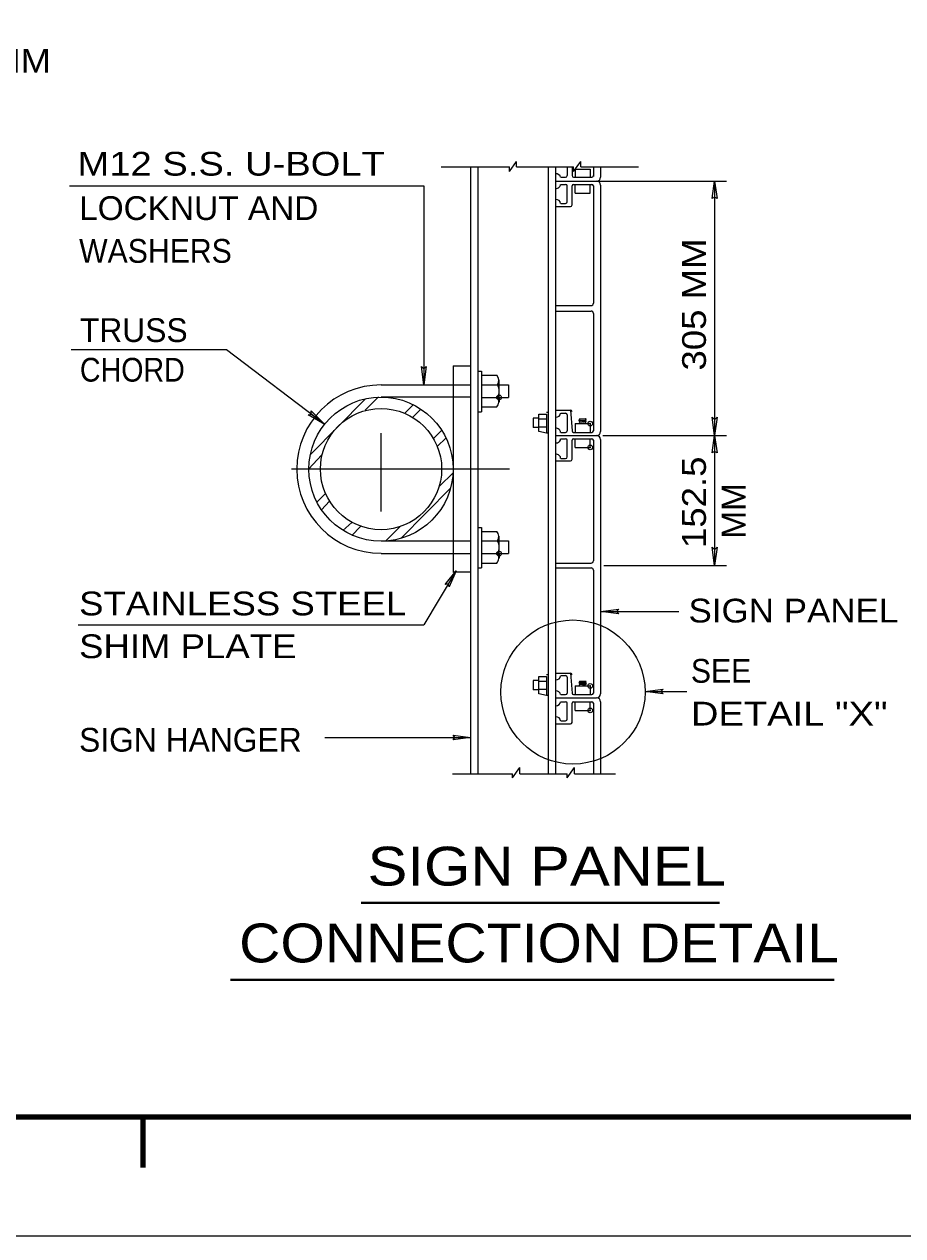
# Model space of a CAD drawing. Extents: x 312601.858 to 312602.699, y 144420.109 to 144420.704.
# Drawn here: x 312602.2633 to 312602.3741, y 144420.1095 to 144420.2624 of the extents above; entities that cross this region are included whole.
import ezdxf
from ezdxf.enums import TextEntityAlignment as Align

# ---------------------------------------------------------------- set-up
doc = ezdxf.new("R2010")
doc.units = 0
doc.header["$LTSCALE"] = 0.0012
doc.header["$PDMODE"] = 32
doc.header["$PDSIZE"] = 0.0006
doc.linetypes.add('DOT_DASHED', pattern=[7.7, 5, -1.2, 0.3, -1.2])
doc.linetypes.add('SHORT_DASHED', pattern=[2.7, 1.5, -1.2])
for name, color, linetype, lineweight in [('1', 7, 'Continuous', 13), ('2', 7, 'Continuous', 13), ('39', 7, 'Continuous', 13)]:
    doc.layers.add(name, color=color, linetype=linetype, lineweight=lineweight)

msp = doc.modelspace()

# ---------------------------------------------------------------- hatches: boundary and pattern name
at = {"layer": '39'}
msp.add_hatch(color=256, dxfattribs=at).paths.add_polyline_path([(312602.2995, 144420.2132), (312602.2995, 144420.2136), (312602.3012, 144420.2119), (312602.2991, 144420.2131)])

# ---------------------------------------------------------------- linework, layer by layer
at = {"layer": '1'}
for p, q in [((312602.3159, 144420.2444), (312602.3245, 144420.2444)), ((312602.3245, 144420.2438), (312602.3254, 144420.2451)), ((312602.3245, 144420.2438), (312602.3245, 144420.2444)), ((312602.3254, 144420.2444), (312602.3254, 144420.2451)), ((312602.3254, 144420.2444), (312602.3326, 144420.2444)), ((312602.3326, 144420.2438), (312602.3335, 144420.2451)), ((312602.3326, 144420.2438), (312602.3326, 144420.2444)), ((312602.3335, 144420.2444), (312602.3335, 144420.2451)), ((312602.3335, 144420.2444), (312602.3408, 144420.2444)), ((312602.3351, 144420.2444), (312602.3351, 144420.2432)), ((312602.3328, 144420.2441), (312602.3328, 144420.2431)), ((312602.3328, 144420.2441), (312602.3347, 144420.2441)), ((312602.3347, 144420.2441), (312602.3347, 144420.2431)), ((312602.269, 144420.242), (312602.3137, 144420.242)), ((312602.3137, 144420.242), (312602.3137, 144420.2169)), ((312602.331, 144420.2422), (312602.3316, 144420.2422)), ((312602.3318, 144420.24), (312602.3318, 144420.242)), ((312602.3328, 144420.2411), (312602.3328, 144420.2422)), ((312602.3328, 144420.2411), (312602.3347, 144420.2411)), ((312602.3347, 144420.2411), (312602.3347, 144420.2422)), ((312602.331, 144420.2398), (312602.3316, 144420.2398)), ((312602.2994, 144420.2081), (312602.3063, 144420.2151)), ((312602.3063, 144420.2137), (312602.308, 144420.2154)), ((312602.3113, 144420.2133), (312602.3124, 144420.2144)), ((312602.3123, 144420.2128), (312602.3133, 144420.2138)), ((312602.3275, 144420.2127), (312602.3275, 144420.2115)), ((312602.3282, 144420.2127), (312602.3275, 144420.2127)), ((312602.3282, 144420.2126), (312602.3292, 144420.2126)), ((312602.3294, 144420.2134), (312602.3292, 144420.2134)), ((312602.331, 144420.2133), (312602.3316, 144420.2133)), ((312602.3318, 144420.2131), (312602.3318, 144420.2111)), ((312602.3333, 144420.2126), (312602.3334, 144420.2126)), ((312602.3333, 144420.2124), (312602.3341, 144420.2124)), ((312602.3334, 144420.2126), (312602.3341, 144420.2126)), ((312602.3334, 144420.2122), (312602.3342, 144420.2123)), ((312602.3149, 144420.2101), (312602.316, 144420.2112)), ((312602.3282, 144420.2115), (312602.3275, 144420.2115)), ((312602.3282, 144420.2116), (312602.3292, 144420.2116)), ((312602.3294, 144420.2108), (312602.3292, 144420.2108)), ((312602.331, 144420.2109), (312602.3316, 144420.2109)), ((312602.3327, 144420.2109), (312602.3349, 144420.2109)), ((312602.3328, 144420.212), (312602.3328, 144420.2109)), ((312602.3328, 144420.212), (312602.3347, 144420.212)), ((312602.3347, 144420.212), (312602.3347, 144420.2109)), ((312602.3363, 144420.2105), (312602.3519, 144420.2105)), ((312602.3154, 144420.2091), (312602.3165, 144420.2102)), ((312602.331, 144420.2101), (312602.3316, 144420.2101)), ((312602.3318, 144420.2078), (312602.3318, 144420.2099)), ((312602.3327, 144420.2101), (312602.3349, 144420.2101)), ((312602.3328, 144420.209), (312602.3328, 144420.2101)), ((312602.3328, 144420.209), (312602.3347, 144420.209)), ((312602.3347, 144420.209), (312602.3347, 144420.2101)), ((312602.2992, 144420.2063), (312602.3008, 144420.208)), ((312602.331, 144420.2076), (312602.3316, 144420.2076)), ((312602.3157, 144420.2041), (312602.3174, 144420.2058)), ((312602.3002, 144420.2021), (312602.3013, 144420.2032)), ((312602.3108, 144420.1975), (312602.3171, 144420.2039)), ((312602.3008, 144420.2011), (312602.3018, 144420.2022)), ((312602.3035, 144420.1985), (312602.3046, 144420.1995)), ((312602.3046, 144420.1979), (312602.3057, 144420.199)), ((312602.3089, 144420.1972), (312602.3107, 144420.199)), ((312602.3364, 144420.1941), (312602.3519, 144420.1941)), ((312602.3177, 144420.1933), (312602.3137, 144420.1866)), ((312602.336, 144420.1883), (312602.3459, 144420.1883)), ((312602.2701, 144420.1866), (312602.3137, 144420.1866)), ((312602.3294, 144420.1803), (312602.3292, 144420.1803)), ((312602.331, 144420.1802), (312602.3316, 144420.1802)), ((312602.3318, 144420.18), (312602.3318, 144420.178)), ((312602.3275, 144420.1796), (312602.3275, 144420.1784)), ((312602.3282, 144420.1796), (312602.3275, 144420.1796)), ((312602.3282, 144420.1784), (312602.3275, 144420.1784)), ((312602.3282, 144420.1795), (312602.3292, 144420.1795)), ((312602.3282, 144420.1785), (312602.3292, 144420.1785)), ((312602.3328, 144420.1789), (312602.3328, 144420.1778)), ((312602.3328, 144420.1789), (312602.3347, 144420.1789)), ((312602.3333, 144420.1794), (312602.3334, 144420.1795)), ((312602.3333, 144420.1792), (312602.3341, 144420.1792)), ((312602.3334, 144420.1795), (312602.3342, 144420.1795)), ((312602.3334, 144420.1793), (312602.3342, 144420.1793)), ((312602.3334, 144420.1791), (312602.3342, 144420.1791)), ((312602.3347, 144420.1789), (312602.3347, 144420.1778)), ((312602.3294, 144420.1777), (312602.3292, 144420.1777)), ((312602.331, 144420.1778), (312602.3316, 144420.1778)), ((312602.331, 144420.1769), (312602.3316, 144420.1769)), ((312602.3327, 144420.1778), (312602.3349, 144420.1778)), ((312602.3328, 144420.1758), (312602.3328, 144420.1769)), ((312602.3347, 144420.1758), (312602.3347, 144420.1769)), ((312602.3416, 144420.1782), (312602.3469, 144420.1782)), ((312602.3318, 144420.1747), (312602.3318, 144420.1767)), ((312602.3328, 144420.1758), (312602.3347, 144420.1758)), ((312602.331, 144420.1745), (312602.3316, 144420.1745)), ((312602.3012, 144420.1724), (312602.3196, 144420.1724)), ((312602.3173, 144420.1678), (312602.3249, 144420.1678)), ((312602.3249, 144420.1673), (312602.3258, 144420.1686)), ((312602.3249, 144420.1673), (312602.3249, 144420.1678)), ((312602.3258, 144420.1678), (312602.3258, 144420.1686)), ((312602.3258, 144420.1678), (312602.3318, 144420.1678)), ((312602.3318, 144420.1673), (312602.3327, 144420.1686)), ((312602.3318, 144420.1673), (312602.3318, 144420.1678)), ((312602.3327, 144420.1678), (312602.3327, 144420.1686)), ((312602.3327, 144420.1678), (312602.3379, 144420.1678))]:
    msp.add_line(p, q, dxfattribs=at)
at = {"layer": '1', "lineweight": 25}
for p, q in [((312602.3196, 144420.2444), (312602.3196, 144420.1678)), ((312602.3205, 144420.2444), (312602.3205, 144420.1678)), ((312602.3294, 144420.2444), (312602.3294, 144420.1678)), ((312602.3303, 144420.2444), (312602.3303, 144420.2272)), ((312602.3318, 144420.2444), (312602.3318, 144420.2433)), ((312602.3324, 144420.2444), (312602.3324, 144420.2433)), ((312602.3351, 144420.2444), (312602.3351, 144420.2433)), ((312602.336, 144420.2444), (312602.336, 144420.2431)), ((312602.3303, 144420.2426), (312602.3355, 144420.2426)), ((312602.331, 144420.2431), (312602.3316, 144420.2431)), ((312602.3326, 144420.2431), (312602.3349, 144420.2431)), ((312602.3324, 144420.2396), (312602.3324, 144420.242)), ((312602.3326, 144420.2422), (312602.3349, 144420.2422)), ((312602.3351, 144420.242), (312602.3351, 144420.2282)), ((312602.3351, 144420.242), (312602.3351, 144420.2272)), ((312602.336, 144420.2421), (312602.336, 144420.211)), ((312602.3303, 144420.2394), (312602.3322, 144420.2394)), ((312602.3303, 144420.2272), (312602.3303, 144420.1947)), ((312602.3303, 144420.2269), (312602.3348, 144420.2269)), ((312602.3303, 144420.2262), (312602.3348, 144420.2262)), ((312602.3351, 144420.2259), (312602.3351, 144420.2111)), ((312602.3351, 144420.2248), (312602.3351, 144420.2111)), ((312602.3174, 144420.2193), (312602.3174, 144420.1932)), ((312602.3174, 144420.2193), (312602.3196, 144420.2193)), ((312602.3205, 144420.2186), (312602.321, 144420.2186)), ((312602.3083, 144420.2169), (312602.3174, 144420.2169)), ((312602.321, 144420.2181), (312602.3229, 144420.2181)), ((312602.321, 144420.2169), (312602.323, 144420.2169)), ((312602.323, 144420.2169), (312602.3232, 144420.2169)), ((312602.3232, 144420.2169), (312602.3232, 144420.2175)), ((312602.3232, 144420.2153), (312602.3232, 144420.2169)), ((312602.3244, 144420.2169), (312602.3244, 144420.2153)), ((312602.3083, 144420.2154), (312602.3174, 144420.2154)), ((312602.323, 144420.2153), (312602.3232, 144420.2153)), ((312602.3232, 144420.2153), (312602.3232, 144420.2147)), ((312602.321, 144420.2141), (312602.3229, 144420.2141)), ((312602.3205, 144420.2135), (312602.321, 144420.2135)), ((312602.3303, 144420.2105), (312602.3357, 144420.2105)), ((312602.3326, 144420.2109), (312602.3349, 144420.2109)), ((312602.3324, 144420.2075), (312602.3324, 144420.2099)), ((312602.3326, 144420.2101), (312602.3349, 144420.2101)), ((312602.3351, 144420.2099), (312602.3351, 144420.1947)), ((312602.336, 144420.21), (312602.336, 144420.1779)), ((312602.3303, 144420.2073), (312602.3322, 144420.2073)), ((312602.3205, 144420.1989), (312602.321, 144420.1989)), ((312602.321, 144420.1984), (312602.3229, 144420.1984)), ((312602.3083, 144420.1972), (312602.3174, 144420.1972)), ((312602.321, 144420.1972), (312602.323, 144420.1972)), ((312602.323, 144420.1972), (312602.3232, 144420.1972)), ((312602.3232, 144420.1972), (312602.3232, 144420.1978)), ((312602.3232, 144420.1956), (312602.3232, 144420.1972)), ((312602.3244, 144420.1972), (312602.3244, 144420.1956)), ((312602.3083, 144420.1956), (312602.3174, 144420.1956)), ((312602.323, 144420.1956), (312602.3232, 144420.1956)), ((312602.3232, 144420.1956), (312602.3232, 144420.195)), ((312602.3205, 144420.1938), (312602.321, 144420.1938)), ((312602.321, 144420.1944), (312602.3229, 144420.1944)), ((312602.3303, 144420.1947), (312602.3303, 144420.1678)), ((312602.3303, 144420.1944), (312602.3348, 144420.1944)), ((312602.3303, 144420.1938), (312602.3348, 144420.1938)), ((312602.3174, 144420.1933), (312602.3196, 144420.1933)), ((312602.3351, 144420.1935), (312602.3351, 144420.178)), ((312602.3351, 144420.1932), (312602.3351, 144420.178)), ((312602.3303, 144420.1774), (312602.3355, 144420.1774)), ((312602.3326, 144420.1778), (312602.3349, 144420.1778)), ((312602.3326, 144420.1769), (312602.3349, 144420.1769)), ((312602.3327, 144420.1769), (312602.3349, 144420.1769)), ((312602.336, 144420.1769), (312602.336, 144420.1678)), ((312602.3324, 144420.1743), (312602.3324, 144420.1767)), ((312602.3351, 144420.1767), (312602.3351, 144420.1678)), ((312602.3303, 144420.1741), (312602.3322, 144420.1741))]:
    msp.add_line(p, q, dxfattribs=at)
at = {"layer": '1', "linetype": 'SHORT_DASHED', "lineweight": 25}
for p, q in [((312602.3174, 144420.2169), (312602.3196, 144420.2169)), ((312602.3174, 144420.2154), (312602.3196, 144420.2154)), ((312602.3174, 144420.1972), (312602.3196, 144420.1972)), ((312602.3174, 144420.1956), (312602.3196, 144420.1956))]:
    msp.add_line(p, q, dxfattribs=at)
at = {"layer": '1', "linetype": 'DOT_DASHED'}
for p, q in [((312602.3083, 144420.2009), (312602.3083, 144420.2108)), ((312602.297, 144420.2063), (312602.3245, 144420.2063))]:
    msp.add_line(p, q, dxfattribs=at)
at = {"layer": '1'}
for points in [[(312602.3303, 144420.2426), (312602.3357, 144420.2426), (312602.3519, 144420.2426)], [(312602.3504, 144420.2426), (312602.3504, 144420.2105), (312602.3504, 144420.1941)], [(312602.3333, 144420.212), (312602.3334, 144420.2122), (312602.3333, 144420.2124), (312602.3334, 144420.2125), (312602.3333, 144420.2126)], [(312602.3333, 144420.212), (312602.3341, 144420.2121), (312602.3341, 144420.2121)], [(312602.3334, 144420.2126), (312602.3342, 144420.2126), (312602.3341, 144420.2126)], [(312602.3341, 144420.2121), (312602.3342, 144420.2123), (312602.3341, 144420.2124), (312602.3342, 144420.2126)], [(312602.3333, 144420.1794), (312602.3341, 144420.1794), (312602.3342, 144420.1791), (312602.3341, 144420.1792)], [(312602.3333, 144420.1789), (312602.3334, 144420.1791), (312602.3333, 144420.1792), (312602.3334, 144420.1793), (312602.3333, 144420.1794)], [(312602.3333, 144420.1789), (312602.3341, 144420.179), (312602.3341, 144420.179)], [(312602.3341, 144420.1792), (312602.3342, 144420.1793), (312602.3341, 144420.1794), (312602.3342, 144420.1795)], [(312602.3303, 144420.1774), (312602.3346, 144420.1774), (312602.3355, 144420.1774)]]:
    msp.add_lwpolyline(points, dxfattribs=at)
for points in [[(312602.3501, 144420.2404), (312602.3504, 144420.2426), (312602.3507, 144420.2404), (312602.3504, 144420.2406)], [(312602.314, 144420.2192), (312602.3137, 144420.2169), (312602.3134, 144420.2192), (312602.3137, 144420.2189)], [(312602.3282, 144420.2132), (312602.3292, 144420.2132), (312602.3292, 144420.2108), (312602.3282, 144420.211)], [(312602.3507, 144420.2128), (312602.3504, 144420.2105), (312602.3501, 144420.2128), (312602.3504, 144420.2125)], [(312602.3501, 144420.2083), (312602.3504, 144420.2105), (312602.3507, 144420.2083), (312602.3504, 144420.2085)], [(312602.3507, 144420.1964), (312602.3504, 144420.1941), (312602.3501, 144420.1964), (312602.3504, 144420.1961)], [(312602.3164, 144420.1917), (312602.3178, 144420.1934), (312602.3169, 144420.1914), (312602.3168, 144420.1918)], [(312602.3383, 144420.188), (312602.336, 144420.1883), (312602.3383, 144420.1886), (312602.338, 144420.1883)], [(312602.3282, 144420.1801), (312602.3292, 144420.1801), (312602.3292, 144420.1777), (312602.3282, 144420.1779)], [(312602.3439, 144420.1779), (312602.3416, 144420.1782), (312602.3439, 144420.1785), (312602.3436, 144420.1782)], [(312602.3174, 144420.1727), (312602.3196, 144420.1724), (312602.3174, 144420.1721), (312602.3176, 144420.1724)]]:
    msp.add_lwpolyline(points, close=True, dxfattribs=at)
at = {"layer": '1', "lineweight": 25}
for points in [[(312602.323, 144420.2169), (312602.3232, 144420.2169), (312602.3244, 144420.2169)], [(312602.321, 144420.2153), (312602.323, 144420.2153), (312602.3244, 144420.2153)], [(312602.3303, 144420.2137), (312602.3322, 144420.2137), (312602.3324, 144420.2111)], [(312602.323, 144420.1972), (312602.3232, 144420.1972), (312602.3244, 144420.1972)], [(312602.321, 144420.1956), (312602.323, 144420.1956), (312602.3244, 144420.1956)], [(312602.3303, 144420.1805), (312602.3322, 144420.1805), (312602.3324, 144420.178)]]:
    msp.add_lwpolyline(points, dxfattribs=at)
for radius in [0.009095, 0.00765]:
    msp.add_circle((312602.3083, 144420.20626), radius, dxfattribs=at)
at = {"layer": '1'}
msp.add_circle((312602.332525, 144420.178125), 0.009095, dxfattribs=at)
at = {"layer": '1', "lineweight": 25}
for centre, radius, start, end in [((312602.3316, 144420.2433), 0.0002, 270, 0), ((312602.3326, 144420.2433), 0.0002, 180, 270), ((312602.3349, 144420.2433), 0.0002, 270, 0), ((312602.3355, 144420.2431), 0.0005, 270, 0), ((312602.3355, 144420.2421), 0.0005, 0, 90), ((312602.3326, 144420.242), 0.0002, 90, 180), ((312602.3349, 144420.242), 0.0002, 0, 90), ((312602.3322, 144420.2396), 0.0002, 270, 0), ((312602.3348, 144420.2272), 0.0003, 270, 0), ((312602.3348, 144420.2259), 0.0003, 0, 90), ((312602.3083, 144420.20626), 0.010625, 90, 270), ((312602.32223, 144420.21746), 0.000939, 323.38244, 42.97513), ((312602.32223, 144420.21746), 0.000939, 323.38244, 2.44183), ((312602.3215, 144420.2161), 0.0017, 331.92751, 28.07248), ((312602.32223, 144420.21474), 0.000939, 357.55817, 36.61756), ((312602.32223, 144420.21474), 0.000939, 317.02487, 356.82121), ((312602.3322, 144420.2135), 0.0002, 0, 90), ((312602.3326, 144420.2111), 0.0002, 180, 270), ((312602.3349, 144420.2111), 0.0002, 270, 0), ((312602.3355, 144420.211), 0.0005, 270, 0), ((312602.3355, 144420.21), 0.0005, 0, 90), ((312602.3326, 144420.2099), 0.0002, 90, 180), ((312602.3349, 144420.2099), 0.0002, 0, 90), ((312602.3322, 144420.2075), 0.0002, 270, 0), ((312602.32223, 144420.19776), 0.000939, 323.38244, 42.97513), ((312602.32223, 144420.19776), 0.000939, 323.38244, 2.44183), ((312602.3215, 144420.1964), 0.0017, 331.92751, 28.07248), ((312602.32223, 144420.19504), 0.000939, 357.55817, 36.61756), ((312602.32223, 144420.19504), 0.000939, 317.02487, 356.82121), ((312602.3348, 144420.1947), 0.0003, 270, 0), ((312602.3348, 144420.1935), 0.0003, 0, 90), ((312602.3322, 144420.1803), 0.0002, 0, 90), ((312602.3326, 144420.178), 0.0002, 180, 270), ((312602.3326, 144420.1767), 0.0002, 90, 180), ((312602.3349, 144420.178), 0.0002, 270, 0), ((312602.3349, 144420.1767), 0.0002, 0.00156, 90), ((312602.3355, 144420.1779), 0.0005, 270, 0), ((312602.3355, 144420.1769), 0.0005, 0, 90), ((312602.3322, 144420.1743), 0.0002, 270, 0)]:
    msp.add_arc(centre, radius, start, end, dxfattribs=at)
at = {"layer": '1'}
for centre, start, end in [((312602.3316, 144420.242), 0, 90), ((312602.3316, 144420.24), 270, 0), ((312602.3316, 144420.2131), 0, 90), ((312602.3316, 144420.2111), 270, 0), ((312602.3316, 144420.2099), 0, 90), ((312602.3316, 144420.2078), 270, 0), ((312602.3316, 144420.18), 0, 90), ((312602.3316, 144420.178), 270, 0), ((312602.3316, 144420.1767), 0, 90), ((312602.3316, 144420.1747), 270, 0)]:
    msp.add_arc(centre, 0.0002, start, end, dxfattribs=at)
at = {"layer": '1', "lineweight": 25}
msp.add_ellipse((312602.330308, 144420.243036), major_axis=(0.000656, 0), ratio=0.777881, start_param=0.1253975, end_param=1.5707963, dxfattribs=at)
at = {"layer": '1'}
for centre, start_param, end_param in [((312602.330308, 144420.242186), 4.712389, 6.3105715), ((312602.330308, 144420.239777), 0.0446785, 1.5707963), ((312602.330308, 144420.213315), 4.712389, 6.2831853), ((312602.330308, 144420.210906), 6.2710267, 7.8539816), ((312602.330308, 144420.210056), 4.712389, 6.3694869), ((312602.330308, 144420.207647), 6.1904888, 7.8539816), ((312602.330308, 144420.180165), 4.712389, 6.2831853), ((312602.330308, 144420.177756), 0.0859671, 1.5707963), ((312602.330308, 144420.176906), 4.712389, 6.2831853), ((312602.330308, 144420.174497), 0, 1.5707963)]:
    msp.add_ellipse(centre, major_axis=(0.000656, 0), ratio=0.777881, start_param=start_param, end_param=end_param, dxfattribs=at)
for p in [(312602.3232, 144420.2153), (312602.3347, 144420.212), (312602.3347, 144420.209), (312602.3232, 144420.1956), (312602.3347, 144420.1789), (312602.3347, 144420.1758)]:
    msp.add_point(p, dxfattribs=at)
at = {"layer": '2', "lineweight": 25}
for p, q in [((312602.321, 144420.2186), (312602.321, 144420.2135)), ((312602.321, 144420.1989), (312602.321, 144420.1938))]:
    msp.add_line(p, q, dxfattribs=at)
at = {"layer": '2', "lineweight": 40}
for p, q in [((312602.3058, 144420.1515), (312602.351, 144420.1515)), ((312602.2893, 144420.1418), (312602.3655, 144420.1418))]:
    msp.add_line(p, q, dxfattribs=at)
at = {"layer": '2'}
msp.add_lwpolyline([(312602.3012, 144420.2119), (312602.2888, 144420.2213), (312602.2692, 144420.2213)], dxfattribs=at)
at = {"layer": '39', "lineweight": 158}
msp.add_line((312602.2783, 144420.1181), (312602.2783, 144420.1245), dxfattribs=at)
msp.add_line((312602.2783, 144420.1181), (312602.2783, 144420.1245), dxfattribs=at)
msp.add_line((312602.2783, 144420.1181), (312602.2783, 144420.1245), dxfattribs=at)
at = {"layer": '39', "lineweight": 25}
msp.add_lwpolyline([(312601.8578, 144420.1095), (312602.6988, 144420.1095), (312602.6988, 144420.7035)], dxfattribs=at)
at = {"layer": '39', "lineweight": 158}
msp.add_lwpolyline([(312601.9088, 144420.1245), (312602.6838, 144420.1245), (312602.6838, 144420.6645)], dxfattribs=at)
at = {"layer": '39'}
msp.add_lwpolyline([(312602.2995, 144420.2132), (312602.2995, 144420.2136), (312602.3012, 144420.2119), (312602.2991, 144420.2131)], close=True, dxfattribs=at)

# ---------------------------------------------------------------- texts
at = {"layer": '2', "width": 1.15}
msp.add_text('50 MM', height=0.003, dxfattribs=at).set_placement((312602.2596, 144420.2563), align=Align.CENTER)
at = {"layer": '2'}
for s, height, width, p in [('M12 S.S. U-BOLT', 0.003, 1.2, (312602.27, 144420.2433)), ('LOCKNUT AND', 0.003, 1.05, (312602.2702, 144420.2377)), ('WASHERS', 0.003, 0.95, (312602.2702, 144420.2323)), ('CHORD', 0.003, 0.9, (312602.2703, 144420.2173)), ('STAINLESS STEEL', 0.003, 1.15, (312602.2702, 144420.1878)), ('SIGN PANEL FACE', 0.003, 1.1, (312602.3471, 144420.1869)), ('SHIM PLATE', 0.003, 1.15, (312602.2702, 144420.1824)), ('SEE', 0.003, 0.95, (312602.3474, 144420.1793)), ('DETAIL "X"', 0.003, 1.2, (312602.3474, 144420.1739)), ('SIGN PANEL ', 0.0049, 1.15, (312602.3066, 144420.1537)), ('CONNECTION DETAIL ', 0.0049, 1.1, (312602.2904, 144420.144))]:
    msp.add_text(s, height=height, dxfattribs=dict(at, width=width)).set_placement(p)
for s, width, p in [('305 MM', 1.15, (312602.3493, 144420.2187)), ('152.5', 1.15, (312602.3493, 144420.1963)), (' MM', 1.05, (312602.3543, 144420.1963))]:
    msp.add_text(s, height=0.003, rotation=90, dxfattribs=dict(at, width=width)).set_placement(p)
for s, p in [('TRUSS', (312602.2703, 144420.2223)), ('SIGN HANGER', (312602.2702, 144420.1706))]:
    msp.add_text(s, height=0.003, dxfattribs=at).set_placement(p)

doc.saveas('drawing.dxf')
